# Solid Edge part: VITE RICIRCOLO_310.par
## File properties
Subject: VITE RICIRCOLO 310
Author: f_grande
Template: Normal.par
Last saved by: f_grande
Revision: 5
Application: Solid Edge
Document Number: KR0125
Densità: 7833,000 kg/m^3
Precisione: 0,990
Tipo di contenuto documento: 0
Material: Acciaio
Stile della faccia: Acciaio
Stile di riempimento: ANSI32(Acciaio)
Stile virtuale: Acciaio lavorato a macchina
Coef. of Thermal Exp: 0.0
Thermal Conductivity: 32.0
Specific Heat: 481.0
Modulus of Elasticity: 199947953000.0
Poisson's Ratio: 0.29
Yield Stress: 262000766.0
Ultimate Stress: 358527364.0
Elongation: 0.0
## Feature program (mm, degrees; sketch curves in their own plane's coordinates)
sketch for "unnamed Protrusion 1" plane through (0, 0, 0) normal (0, -1, 0) x-axis (1, 0, 0)
  circle centre (0, 0) radius 8
extrude "unnamed Protrusion 1" add finite 310 along -normal
sketch for "ExtrudedCutout_1" #1 plane through (0, 0, 0) normal (0, -1, 0) x-axis (1, 0, 0)
  circle centre (0, 0) radius 5
sketch for "ExtrudedCutout_1" #2 plane through (0, 0, 0) normal (0, -1, 0) x-axis (1, 0, 0)
  circle centre (0, 0) radius 9.8339
extrude "ExtrudedCutout_1" cut finite 12 along -normal
sketch for "unnamed RevolvedCutout 1" plane through (0, 0, 0) normal (1, 0, 0) x-axis (0, 1, 0)
  line (3, 5) -> (4.1, 5)
  line (4.1, 5) -> (4.1, 4.6)
  line (4.1, 4.6) -> (3, 4.6)
  line (3, 4.6) -> (3, 5)
  dimension (linear) = 3
  dimension (linear) = 4.1
revolve "unnamed RevolvedCutout 1" cut full turn 360 deg
helix cutout "HelixCutout_2"  Pitch = 5 mm
sketch for "ExtrudedCutout_2" #1 plane through (0, 310, 0) normal (0, 1, 0) x-axis (-1, 0, 0)
  circle centre (0, 0) radius 6
sketch for "ExtrudedCutout_2" #2 plane through (0, 310, 0) normal (0, 1, 0) x-axis (-1, 0, 0)
  circle centre (0, 0) radius 9.9648
extrude "ExtrudedCutout_2" cut finite 54 along -normal
sketch for "ExtrudedCutout_3" #1 plane through (0, 310, 0) normal (0, 1, 0) x-axis (-1, 0, 0)
  circle centre (0, 0) radius 5
sketch for "ExtrudedCutout_3" #2 plane through (0, 310, 0) normal (0, 1, 0) x-axis (-1, 0, 0)
  circle centre (0, 0) radius 10.6518
extrude "ExtrudedCutout_3" cut finite 16 along -normal
thread "Filettatura_3"  ThreadDepth = 16 mm
chamfer "Smusso_1" setback 1
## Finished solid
Body 1: solid body, 18 faces, 20 edges, 4 vertices.
  Faces by surface: plane 9, cylinder 7, cone 1, spline 1
  Edges by curve: circle 16, line 2, spline 2
Bounding box of the edges (mm; curved faces can reach further): 16.000 x 310.000 x 16.000, from (-8, 0, -8) to (8, 310, 8).
Cylindrical faces by radius (mm): R4.6 x1, R5 x3, R6 x2, R8 x1
Conical faces (half-angle, radius in mm at the cone's reference point): 45 deg R5 x1
Planar faces by outward normal: +x 1, +y 4, -x 1, -y 3
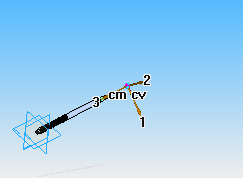
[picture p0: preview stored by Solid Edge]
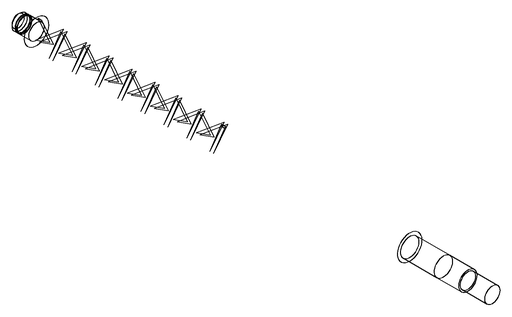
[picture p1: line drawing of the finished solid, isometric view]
